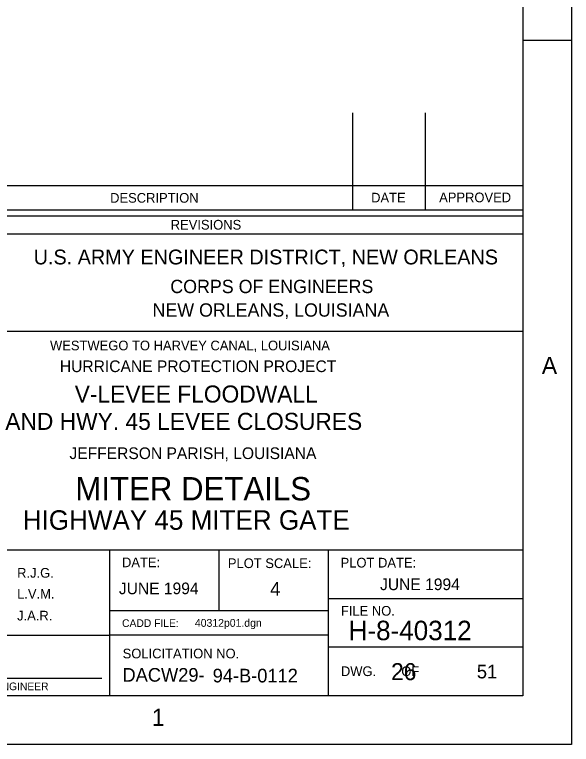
# Model space of a CAD drawing. Extents: x 0.1 to 13.5, y 0.1 to 9.5.
# Drawn here: x 11.549 to 13.458, y 0.125 to 2.629 of the extents above; entities that cross this region are included whole.
import ezdxf

# ---------------------------------------------------------------- set-up
doc = ezdxf.new("R2010")
doc.units = 0
doc.layers.add('Level 1', color=7, linetype='Continuous')
doc.layers.add('Level 2', color=7, linetype='Continuous')

msp = doc.modelspace()

# ---------------------------------------------------------------- linework, layer by layer
at = {"layer": 'Level 1'}
for p, q in [((13.2917, 2.5417), (13.4583, 2.5417)), ((12.7083, 1.9583), (12.7083, 2.2917)), ((12.9583, 1.9583), (12.9583, 2.2917)), ((13.2917, 2.0417), (11.125, 2.0417)), ((13.2917, 1.9583), (11.125, 1.9583)), ((13.2917, 1.9375), (11.125, 1.9375)), ((13.2917, 1.875), (11.125, 1.875)), ((13.2917, 1.5417), (11.125, 1.5417)), ((13.2917, 0.7917), (11.125, 0.7917)), ((11.875, 0.2917), (11.875, 0.7917)), ((12.25, 0.5833), (12.25, 0.7917)), ((12.625, 0.2917), (12.625, 0.7917)), ((13.2917, 0.625), (12.625, 0.625)), ((12.625, 0.5833), (11.875, 0.5833)), ((11.125, 0.5), (11.875, 0.5)), ((12.625, 0.5), (11.875, 0.5)), ((13.2917, 0.4583), (12.625, 0.4583)), ((11.1474, 0.3528), (11.8484, 0.3528))]:
    msp.add_line(p, q, dxfattribs=at)
for points in [[(0.125, 9.4583), (13.4583, 9.4583), (13.4583, 0.125), (0.125, 0.125)], [(0.625, 9.2917), (13.2917, 9.2917), (13.2917, 0.2917), (0.625, 0.2917)]]:
    msp.add_lwpolyline(points, close=True, dxfattribs=at)

# ---------------------------------------------------------------- texts
for s, height, p in [('DESCRIPTION', 0.033208, (11.8763, 1.9835)), ('DATE', 0.03321, (12.7715, 1.9843)), ('APPROVED', 0.03321, (13.0048, 1.985)), ('REVISIONS', 0.03321, (12.0841, 1.8913)), ('U.S. ARMY ENGINEER DISTRICT, NEW ORLEANS', 0.050792, (11.6141, 1.7718)), ('CORPS OF ENGINEERS', 0.045713, (12.0827, 1.6733)), ('NEW ORLEANS, LOUISIANA', 0.045713, (12.0217, 1.5925)), ('A', 0.0584, (13.3571, 1.3961)), ('DATE:', 0.03321, (11.917, 0.7329)), ('PLOT SCALE:', 0.033208, (12.2802, 0.73)), ('PLOT DATE:', 0.03321, (12.6668, 0.7319)), ('FILE NO.', 0.03321, (12.6678, 0.5667)), ('CADD FILE:', 0.02642, (11.9173, 0.5278)), ('SOLICITATION NO.', 0.033208, (11.9193, 0.4202)), ('DACW29-', 0.04679, (11.9187, 0.3402)), ('DWG.       OF', 0.033208, (12.6678, 0.3595)), ('DESIGN ENGINEER', 0.026417, (11.3353, 0.3109)), ('1', 0.0584, (12.0192, 0.1887))]:
    msp.add_text(s, height=height, dxfattribs=at).set_placement(p)
at = {"layer": 'Level 2'}
for s, height, p in [('WESTWEGO TO HARVEY CANAL, LOUISIANA', 0.033208, (11.6702, 1.477)), ('HURRICANE PROTECTION PROJECT', 0.04, (11.7039, 1.4023)), ('V-LEVEE FLOODWALL', 0.058417, (11.7549, 1.2979)), ('AND HWY. 45 LEVEE CLOSURES', 0.058417, (11.5167, 1.2041)), ('JEFFERSON PARISH, LOUISIANA', 0.04, (11.7368, 1.104)), ('MITER DETAILS', 0.08, (11.757, 0.9623)), ('HIGHWAY 45 MITER GATE', 0.066792, (11.5767, 0.8614)), ('R.J.G.', 0.03321, (11.5573, 0.697)), ('JUNE 1994', 0.04, (11.9062, 0.6403)), ('4', 0.0468, (12.4254, 0.6354)), ('JUNE 1994', 0.04, (12.8021, 0.6543)), ('L.V.M.', 0.03321, (11.5573, 0.6252)), ('J.A.R.', 0.03321, (11.5573, 0.5502)), ('40312p01.dgn', 0.026792, (12.1671, 0.5285)), ('H-8-40312', 0.06679, (12.6942, 0.4825)), ('26', 0.05842, (12.8398, 0.3454)), ('94-B-0112', 0.04679, (12.228, 0.3377)), ('51', 0.04679, (13.1341, 0.3515))]:
    msp.add_text(s, height=height, dxfattribs=at).set_placement(p)

doc.saveas('drawing.dxf')
